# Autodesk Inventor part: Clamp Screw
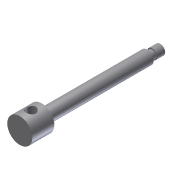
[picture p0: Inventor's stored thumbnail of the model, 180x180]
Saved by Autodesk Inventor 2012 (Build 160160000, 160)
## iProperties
Shininess: 77.0
Length Units: 11269
Angle Units: 11279
Time Units: 11290
Mass Units: 11283
Length Display Precision: 3
Angle Display Precision: 2
Created: 2002-02
Part Number: Clamp Screw
Document SubType Name: Modeling
Designer: ***
Density: 1 g/cm^3
Material: Default
Mass: 23.444 g
Surface Area: 81.4202 cm^2
Volume: 23.444 cm^3
Density: 0.0
Volumn: 0.0
Area: 0.0
PropertySet Name: Model Information
Control State: 0
Master: False
Checked Out: False
Author: ***
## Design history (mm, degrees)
sketch "Sketch1"
  geometry: L1 (0, 140)-(5, 140); L2 (5, 140)-(5, 132); L3 (5, 132)-(4, 132); L4 (4, 132)-(4, 127); L5 (4, 127)-(6.5, 127); L6 (6.5, 127)-(6.5, 25); L7 (6.5, 25)-(4, 25); L8 (4, 25)-(4, 22); L9 (4, 22)-(12.5, 22); L10 (12.5, 22)-(12.5, 0); L11 (12.5, 0)-(0, 0); L12 (0, 0)-(0, 140)
  constraints: 24 end point, 10 parallel, 1 horizontal, 1 perpendicular
  dimensions: "d0" = 10 diameter of L2 L12; "d1" = 8 diameter of L4 L12; "d2" = 13 diameter of L6 L12; "d3" = 8 diameter of L7.end L12; "d4" = 25 diameter of L10 L12; "d5" = 3 distance from line of L7.end L9; "d6" = 8 distance of L1.end L2.end; "d7" = 13 vertical distance of L1.end L5.end; "d8" = 22 distance of L9.end L10.end; "d10" = 102 distance of L5.end L6.end
revolve "Revolution1" sketch "Sketch1" stored, may be unused: angle "d11" = 90 deg
sketch "Sketch3"
  geometry: L1 (-12.5, 0)-(12.5, 0) reference; C1 r 5 at (-0.113, 11)
  constraints: 1 centre point
  dimensions: "d13" = 10 diameter of C1; "d14" = 11 distance from line of L1 C1.centre
extrude "Extrusion1" cut sketch "Sketch3" stored distance "d15" = 10; taper "d16" = 0 deg
body "Solid1"
